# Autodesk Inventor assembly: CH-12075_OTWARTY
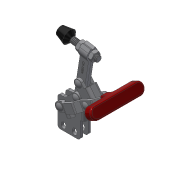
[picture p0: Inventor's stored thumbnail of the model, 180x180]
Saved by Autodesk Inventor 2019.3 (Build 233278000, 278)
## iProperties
Company: Î¢ÈíÖÐ¹ú
Created: 2015-08
Part Number: CH-12075_OTWARTY
Material: Ogólny
Description: STEP AP203
Document SubType Name: Assembly
Designer: CADENGINEERING4
Sending System: SolidWorks 2012
Preprocessor: SwSTEP 2.0
Title: CH-12075.STEP
Author: Î¢ÈíÓÃ»§
Revision Number: ÈÎºÎ
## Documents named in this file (9)
- D:\Vault_2016\Projekty\NASZ KATALOG\CLAMPTEK\STRONA\Vertical toggle clamp\CH-12075\CH-12075_OTWARTY.iam
- D:\Vault_2016\Projekty\NASZ KATALOG\CLAMPTEK\STEP FILES\Vertical toggle clamp\CH-12075\CH-12055-01 STRAIGHT BASE.ipt
- D:\Vault_2016\Projekty\NASZ KATALOG\CLAMPTEK\STEP FILES\Vertical toggle clamp\CH-12075\CH-12075-02 FIXED SPINDLE.ipt
- D:\Vault_2016\Projekty\NASZ KATALOG\CLAMPTEK\STEP FILES\Vertical toggle clamp\CH-12075\CH-12070-03 T-HANDLE.ipt
- D:\Vault_2016\Projekty\NASZ KATALOG\CLAMPTEK\STEP FILES\Vertical toggle clamp\CH-12075\CH-12050-07.ipt
- D:\Vault_2016\Projekty\NASZ KATALOG\CLAMPTEK\STEP FILES\Vertical toggle clamp\CH-12075\CH-12050-06.ipt
- D:\Vault_2016\Projekty\NASZ KATALOG\CLAMPTEK\STEP FILES\Vertical toggle clamp\CH-12075\CH-12050-04 CONNECTING-PLATE.ipt
- D:\Vault_2016\Projekty\NASZ KATALOG\CLAMPTEK\STEP FILES\Vertical toggle clamp\CH-12075\CH-FC-14134 Nut.ipt
- D:\Vault_2016\Projekty\NASZ KATALOG\CLAMPTEK\STEP FILES\Vertical toggle clamp\CH-12075\CH-FC-14134 SPINDLE SUPPLIED.ipt
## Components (11 placed, 8 different names)
1. CH-12055-01 STRAIGHT BASE_1
2. CH-12075-02 FIXED SPINDLE:2 — Zestawiające:5, Zestawiające:8, Zestawiające:15, Zestawiające:19, Zestawiające:20, Zestawiające:21, Równoległe:1
3. CH-12070-03 T-HANDLE:2 — Zestawiające:1, Zestawiające:2, Zestawiające:3, Zestawiające:9, Zestawiające:12, Zestawiające:13, Zestawiające:14
4. CH-12050-07:3 — Zestawiające:4, Zestawiające:5, Zestawiające:6, Zestawiające:7
5. CH-12050-07:4 — Zestawiające:15, Zestawiające:16
6. CH-12050-06:3 — Zestawiające:1, Zestawiające:2, Zestawiające:3
7. CH-12050-04 CONNECTING-PLATE:2 — Zestawiające:4, Zestawiające:6, Zestawiające:7, Zestawiające:8, Zestawiające:9, Zestawiające:10, Zestawiające:11, Zestawiające:16
8. CH-12050-06:4 — Zestawiające:10, Zestawiające:11, Zestawiające:12, Zestawiające:13, Zestawiające:14
9. CH-FC-14134 Nut:3 — Zestawiające:18, Zestawiające:19, Zestawiające:20
10. CH-FC-14134 SPINDLE SUPPLIED:2 — Zestawiające:17, Równoległe:1
11. CH-FC-14134 Nut:4 — Zestawiające:17, Zestawiające:18, Zestawiające:21
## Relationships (22: Mate 21, Flush 1)
- Zestawiające:1 [Mate]: CH-12070-03 T-HANDLE:2 ↔ CH-12050-06:3
- Zestawiające:2 [Mate]: CH-12070-03 T-HANDLE:2 ↔ CH-12050-06:3
- Zestawiające:3 [Mate]: CH-12070-03 T-HANDLE:2 ↔ CH-12050-06:3
- Zestawiające:4 [Mate]: CH-12050-07:3 ↔ CH-12050-04 CONNECTING-PLATE:2
- Zestawiające:5 [Mate]: CH-12075-02 FIXED SPINDLE:2 ↔ CH-12050-07:3
- Zestawiające:6 [Mate]: CH-12050-07:3 ↔ CH-12050-04 CONNECTING-PLATE:2
- Zestawiające:7 [Mate]: CH-12050-07:3 ↔ CH-12050-04 CONNECTING-PLATE:2
- Zestawiające:8 [Mate]: CH-12075-02 FIXED SPINDLE:2 ↔ CH-12050-04 CONNECTING-PLATE:2
- Zestawiające:9 [Mate]: CH-12070-03 T-HANDLE:2 ↔ CH-12050-04 CONNECTING-PLATE:2
- Zestawiające:10 [Mate]: CH-12050-04 CONNECTING-PLATE:2 ↔ CH-12050-06:4
- Zestawiające:11 [Mate]: CH-12050-04 CONNECTING-PLATE:2 ↔ CH-12050-06:4
- Zestawiające:12 [Mate]: CH-12070-03 T-HANDLE:2 ↔ CH-12050-06:4
- Zestawiające:13 [Mate]: CH-12070-03 T-HANDLE:2 ↔ CH-12050-06:4
- Zestawiające:14 [Mate]: CH-12070-03 T-HANDLE:2 ↔ CH-12050-06:4
- Zestawiające:15 [Mate]: CH-12075-02 FIXED SPINDLE:2 ↔ CH-12050-07:4
- Zestawiające:16 [Mate]: CH-12050-07:4 ↔ CH-12050-04 CONNECTING-PLATE:2
- Zestawiające:17 [Mate]: CH-FC-14134 SPINDLE SUPPLIED:2 ↔ CH-FC-14134 Nut:4
- Zestawiające:18 [Mate]: CH-FC-14134 Nut:3 ↔ CH-FC-14134 Nut:4
- Zestawiające:19 [Mate]: CH-12075-02 FIXED SPINDLE:2 ↔ CH-FC-14134 Nut:3
- Zestawiające:20 [Mate]: CH-12075-02 FIXED SPINDLE:2 ↔ CH-FC-14134 Nut:3
- Zestawiające:21 [Mate]: CH-12075-02 FIXED SPINDLE:2 ↔ CH-FC-14134 Nut:4
- Równoległe:1 [Flush]: CH-12075-02 FIXED SPINDLE:2 ↔ CH-FC-14134 SPINDLE SUPPLIED:2
